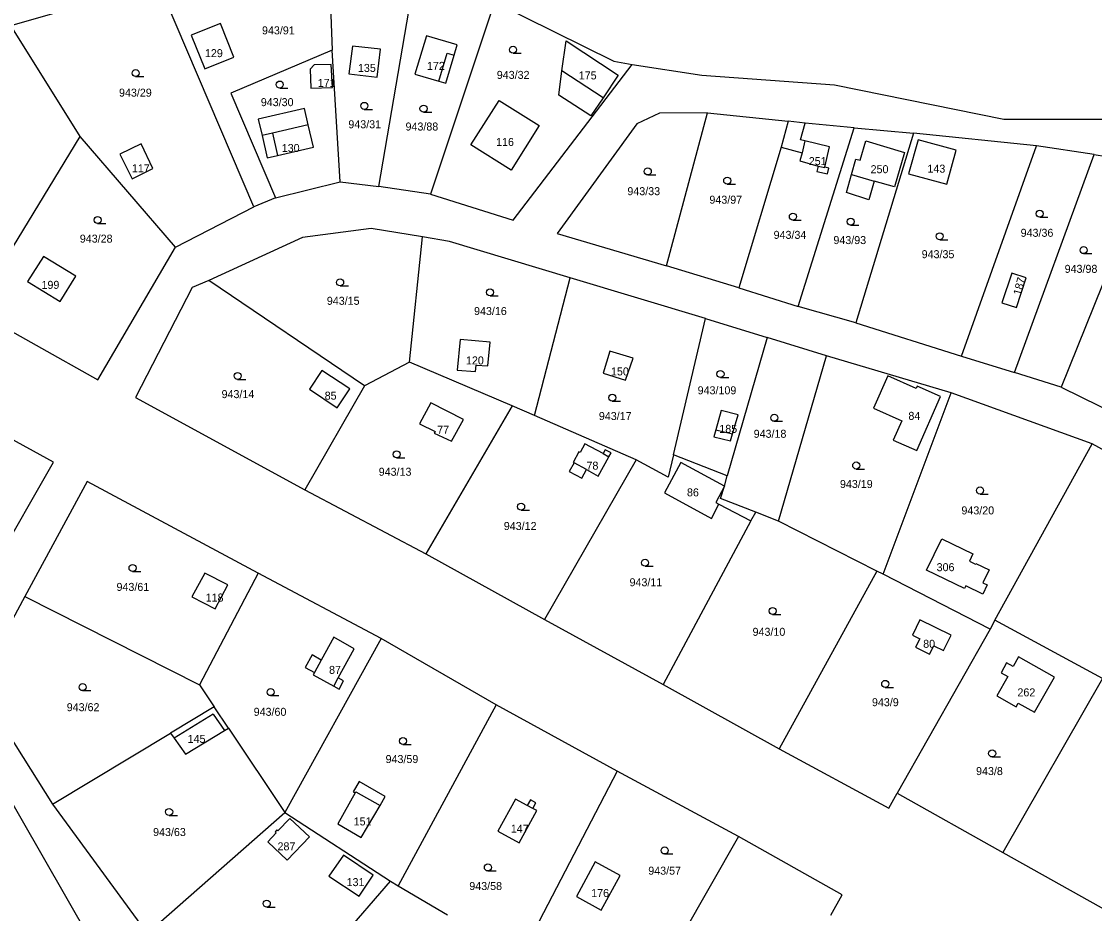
# Model space of a CAD drawing. Extents: x -7476540 to -746055, y -11317203 to -1129777.
# Drawn here: x -751034.6 to -750806.6, y -1131087 to -1130897.4 of the extents above; entities that cross this region are included whole.
import ezdxf

# ---------------------------------------------------------------- set-up
doc = ezdxf.new("R2010")
doc.units = 0
for name, color, linetype in [('Hranice parcel', 7, 'Continuous'), ('Parcelní čísla', 7, 'Continuous'), ('Vnitřní kresba', 7, 'Continuous'), ('Značky kultur', 7, 'Continuous')]:
    doc.layers.add(name, color=color, linetype=linetype)

msp = doc.modelspace()

# ---------------------------------------------------------------- linework, layer by layer
at = {"layer": 'Hranice parcel'}
for p, q in [((-750969.18, -1130887.14), (-750968.63, -1130903.54)), ((-750958.66, -1130932.52), (-750951.18, -1130888.7)), ((-750985.26, -1130936.86), (-751005.24, -1130889.84)), ((-750934.14, -1130893.34), (-750947.69, -1130934.14)), ((-751022.16, -1130921.87), (-751036.87, -1130898.28)), ((-750966.91, -1130931.52), (-750968.63, -1130903.54)), ((-750897.58, -1130949.39), (-750888.87, -1130916.82)), ((-750888.87, -1130916.82), (-750871.74, -1130918.63)), ((-750871.74, -1130918.63), (-750873.22, -1130924.17)), ((-750868.06, -1130919.04), (-750871.74, -1130918.63)), ((-750869.57, -1130958.01), (-750857.66, -1130920.05)), ((-750869.06, -1130922.58), (-750868.06, -1130919.04)), ((-750857.66, -1130920.05), (-750868.06, -1130919.04)), ((-750857.66, -1130920.05), (-750845.08, -1130921.17)), ((-751044.65, -1130958.85), (-751022.16, -1130921.87)), ((-751001.86, -1130945.4), (-751022.16, -1130921.87)), ((-750845.08, -1130921.17), (-750857.31, -1130961.48)), ((-750818.91, -1130923.88), (-750845.08, -1130921.17)), ((-750873.22, -1130924.17), (-750882.2, -1130954.06)), ((-750873.22, -1130924.17), (-750868.74, -1130925.37)), ((-750834.85, -1130968.55), (-750818.91, -1130923.88)), ((-750806.68, -1130925.7), (-750818.91, -1130923.88)), ((-750823.61, -1130972.01), (-750806.68, -1130925.7)), ((-750806.68, -1130925.7), (-750794.6, -1130927.65)), ((-750794.6, -1130927.65), (-750813.68, -1130975.17)), ((-750980.66, -1130934.91), (-750966.91, -1130931.52)), ((-750966.91, -1130931.52), (-750958.66, -1130932.52)), ((-750947.69, -1130934.14), (-750958.66, -1130932.52)), ((-750980.66, -1130934.91), (-750985.26, -1130936.86)), ((-751001.86, -1130945.4), (-750985.26, -1130936.86)), ((-750952.14, -1130969.83), (-750949.38, -1130943.23)), ((-750882.2, -1130954.06), (-750897.58, -1130949.39)), ((-750961.75, -1130974.86), (-750994.79, -1130952.5)), ((-750925.62, -1130981.15), (-750918.05, -1130951.93)), ((-750889.25, -1130960.56), (-750918.05, -1130951.93)), ((-750882.2, -1130954.06), (-750869.57, -1130958.01)), ((-750857.31, -1130961.48), (-750869.57, -1130958.01)), ((-750896.06, -1130989.54), (-750889.25, -1130960.56)), ((-750889.25, -1130960.56), (-750876.18, -1130964.61)), ((-750857.31, -1130961.48), (-750834.85, -1130968.55)), ((-750876.18, -1130964.61), (-750884.66, -1130993.96)), ((-750863.54, -1130968.52), (-750876.18, -1130964.61)), ((-750873.79, -1131003.61), (-750863.54, -1130968.52)), ((-750837.1, -1130976.34), (-750863.54, -1130968.52)), ((-750834.85, -1130968.55), (-750823.61, -1130972.01)), ((-750952.14, -1130969.83), (-750961.75, -1130974.86)), ((-750930.33, -1130979.14), (-750952.14, -1130969.83)), ((-750813.68, -1130975.17), (-750823.61, -1130972.01)), ((-750961.75, -1130974.86), (-750974.42, -1130996.93)), ((-750813.68, -1130975.17), (-750795.61, -1130984.09)), ((-750851.49, -1131014.91), (-750837.1, -1130976.34)), ((-750807.12, -1130987.17), (-750837.1, -1130976.34)), ((-750930.33, -1130979.14), (-750948.69, -1131010.54)), ((-750925.62, -1130981.15), (-750930.33, -1130979.14)), ((-750903.97, -1130990.58), (-750925.62, -1130981.15)), ((-750827.77, -1131024.65), (-750807.12, -1130987.17)), ((-750783.73, -1131000.19), (-750807.12, -1130987.17)), ((-750903.97, -1130990.58), (-750923.45, -1131024.54)), ((-750884.66, -1130993.96), (-750896.06, -1130989.54)), ((-750885.24, -1130996.18), (-750884.66, -1130993.96)), ((-750974.42, -1130996.93), (-750948.69, -1131010.54)), ((-750886.05, -1130998.79), (-750885.24, -1130996.18)), ((-750886.41, -1131000.03), (-750879.66, -1131003.56)), ((-750878.6, -1131001.68), (-750886.05, -1130998.79)), ((-750879.66, -1131003.56), (-750878.6, -1131001.68)), ((-750873.79, -1131003.61), (-750878.6, -1131001.68)), ((-750879.66, -1131003.56), (-750898.3, -1131038.31)), ((-750852.85, -1131014.22), (-750873.79, -1131003.61)), ((-750948.69, -1131010.54), (-750923.45, -1131024.54)), ((-750852.85, -1131014.22), (-750873.59, -1131052.03)), ((-750851.49, -1131014.91), (-750852.85, -1131014.22)), ((-750984.35, -1131014.65), (-750996.76, -1131038.41)), ((-750958.19, -1131028.57), (-750984.35, -1131014.65)), ((-750828.81, -1131026.54), (-750851.49, -1131014.91)), ((-751033.91, -1131019.65), (-750996.76, -1131038.41)), ((-750923.45, -1131024.54), (-750898.3, -1131038.31)), ((-750827.77, -1131024.65), (-750828.81, -1131026.54)), ((-750804.91, -1131037.07), (-750827.77, -1131024.65)), ((-750828.81, -1131026.54), (-750848.52, -1131061.45)), ((-750958.19, -1131028.57), (-750978.69, -1131065.52)), ((-750933.77, -1131042.65), (-750958.19, -1131028.57)), ((-750972.85, -1131032.05), (-750974.36, -1131034.71)), ((-751017.03, -1131097.62), (-751052.97, -1131035.02)), ((-750804.91, -1131037.07), (-750826.11, -1131074)), ((-750996.76, -1131038.41), (-750993.65, -1131043.08)), ((-750967.13, -1131039.32), (-750966.16, -1131037.56)), ((-750898.3, -1131038.31), (-750873.59, -1131052.03)), ((-750993.65, -1131043.08), (-751002.95, -1131048.67)), ((-750990.66, -1131047.57), (-750993.65, -1131043.08)), ((-750933.77, -1131042.65), (-750954.6, -1131081.11)), ((-750908.02, -1131056.72), (-750933.77, -1131042.65)), ((-750990.66, -1131047.57), (-750978.69, -1131065.52)), ((-751028.03, -1131063.75), (-751002.95, -1131048.67)), ((-750908.02, -1131056.72), (-750928.66, -1131096.41)), ((-750882.26, -1131070.62), (-750908.02, -1131056.72)), ((-750848.52, -1131061.45), (-750826.11, -1131074)), ((-751028.03, -1131063.75), (-751007.91, -1131091.26)), ((-751007.91, -1131091.26), (-750978.69, -1131065.52)), ((-750978.69, -1131065.52), (-750956.17, -1131080.13)), ((-750882.26, -1131070.62), (-750894.32, -1131091.73)), ((-750826.11, -1131074), (-750803.42, -1131086.7)), ((-750984.53, -1131112.67), (-750956.17, -1131080.13)), ((-750956.17, -1131080.13), (-750954.6, -1131081.11)), ((-750954.6, -1131081.11), (-750944.07, -1131087.29))]:
    msp.add_line(p, q, dxfattribs=at)
for points in [[(-751036.87, -1130898.28), (-751009.76, -1130890.51), (-751005.24, -1130889.84)], [(-750934.14, -1130893.34), (-750908.78, -1130905.87), (-750904.82, -1130906.58)], [(-750995.69, -1130907.5), (-750989.48, -1130905), (-750992.34, -1130897.88), (-750998.56, -1130900.34), (-750995.69, -1130907.5)], [(-750945.92, -1130910.13), (-750944.45, -1130910.56), (-750942.7, -1130904.58), (-750942.06, -1130902.4), (-750948.54, -1130900.5), (-750951.06, -1130908.63), (-750945.92, -1130910.13)], [(-750911.04, -1130913.69), (-750913.64, -1130917.5), (-750920.43, -1130913.08), (-750919.77, -1130907.92), (-750918.88, -1130901.55), (-750907.81, -1130908.85), (-750911.04, -1130913.69)], [(-750968.63, -1130903.54), (-750990.11, -1130912.67), (-750980.66, -1130934.91)], [(-750958.32, -1130903.33), (-750964.26, -1130902.66), (-750965.03, -1130908.53), (-750959.03, -1130909.3), (-750958.32, -1130903.33)], [(-750973.12, -1130911.62), (-750968.5, -1130911.5), (-750968.79, -1130906.6), (-750972.45, -1130906.68), (-750973.28, -1130907.6), (-750973.12, -1130911.62)], [(-750947.69, -1130934.14), (-750930.15, -1130939.69), (-750904.82, -1130906.58)], [(-750904.82, -1130906.58), (-750890.06, -1130908.85), (-750861.88, -1130910.89), (-750825.89, -1130918.18), (-750800.92, -1130918.19), (-750785.63, -1130919.17), (-750761.64, -1130926.26)], [(-750973.69, -1130919.4), (-750974.49, -1130915.95), (-750984.3, -1130918.23), (-750983.48, -1130921.68)], [(-750939.1, -1130923.63), (-750933.1, -1130914.23), (-750924.58, -1130919.52), (-750930.58, -1130929.06), (-750939.1, -1130923.63)], [(-750888.87, -1130916.82), (-750899.04, -1130916.95), (-750903.89, -1130919.17), (-750920.77, -1130942.5), (-750897.58, -1130949.39)], [(-750983.48, -1130921.68), (-750982.39, -1130926.43), (-750980.22, -1130925.92), (-750972.58, -1130924.14), (-750973.69, -1130919.4)], [(-750868.74, -1130925.37), (-750869.2, -1130927.08), (-750865.31, -1130928.15), (-750865.58, -1130929.3), (-750863.33, -1130929.84), (-750863.03, -1130928.59), (-750863.91, -1130928.38), (-750862.9, -1130924.09), (-750868.13, -1130922.81), (-750869.06, -1130922.58)], [(-750856.4, -1130926.94), (-750855.2, -1130922.78), (-750846.97, -1130925.25), (-750849.09, -1130932.6), (-750853.4, -1130931.35), (-750854.55, -1130935.32), (-750859.34, -1130933.8), (-750858.25, -1130929.94), (-750857.33, -1130926.68), (-750856.4, -1130926.94)], [(-750836.04, -1130924.79), (-750844.11, -1130922.6), (-750846.12, -1130929.84)], [(-751009.17, -1130923.45), (-751013.72, -1130925.66), (-751011.1, -1130930.86), (-751006.69, -1130928.65), (-751009.17, -1130923.45)], [(-750846.12, -1130929.84), (-750838, -1130932.02), (-750836.04, -1130924.79)], [(-750949.38, -1130943.23), (-750960.34, -1130941.46), (-750974.91, -1130943.37), (-750994.79, -1130952.5)], [(-750918.05, -1130951.93), (-750943.66, -1130944.22), (-750949.38, -1130943.23)], [(-751044.65, -1130958.85), (-751018.39, -1130973.56), (-751001.86, -1130945.4)], [(-751026.43, -1130956.96), (-751023.09, -1130951.59), (-751029.93, -1130947.37), (-751033.35, -1130952.7), (-751026.43, -1130956.96)], [(-750994.79, -1130952.5), (-750998.32, -1130953.99), (-751010.42, -1130977.33), (-750974.42, -1130996.93)], [(-750826.29, -1130957.25), (-750823.21, -1130958.25), (-750821.14, -1130951.88), (-750824.19, -1130950.89), (-750826.29, -1130957.25)], [(-750935.51, -1130970.64), (-750935.02, -1130965.55), (-750941.4, -1130965.02), (-750942.04, -1130971.53), (-750938.15, -1130971.85), (-750938, -1130970.48), (-750935.51, -1130970.64)], [(-750911.02, -1130972.18), (-750906.25, -1130973.67), (-750904.61, -1130968.95), (-750909.57, -1130967.48), (-750911.02, -1130972.18)], [(-750964.83, -1130975.53), (-750970.78, -1130971.59), (-750973.43, -1130975.59), (-750967.51, -1130979.57), (-750964.83, -1130975.53)], [(-750853.57, -1130979.6), (-750847.54, -1130982.3), (-750849.38, -1130986.41), (-750844.38, -1130988.59), (-750839.37, -1130977.1), (-750844.3, -1130974.95), (-750844.5, -1130975.41), (-750850.55, -1130972.73), (-750853.57, -1130979.6)], [(-751052.97, -1131035.02), (-751027.78, -1130991.05), (-751058.52, -1130974.24)], [(-750950.02, -1130982.94), (-750946.72, -1130984.59), (-750946.9, -1130984.93), (-750943.27, -1130986.62), (-750940.72, -1130982.05), (-750947.62, -1130978.45), (-750950.02, -1130982.94)], [(-750885.94, -1130980.07), (-750887.07, -1130984.22), (-750887.47, -1130985.68), (-750883.97, -1130986.56), (-750883.52, -1130985.08), (-750882.3, -1130980.99), (-750885.94, -1130980.07)], [(-750912.05, -1130994.03), (-750909.81, -1130989.94), (-750909.35, -1130989.1), (-750910.58, -1130988.43), (-750911.04, -1130989.27), (-750914.89, -1130987.18), (-750915.93, -1130989.02), (-750916.19, -1130988.87), (-750917.37, -1130991.13), (-750917.19, -1130991.23), (-750918.23, -1130993.06), (-750915.56, -1130994.5), (-750914.57, -1130992.65), (-750912.05, -1130994.03)], [(-750896.06, -1130989.54), (-750897.17, -1130994.27), (-750903.97, -1130990.58)], [(-750885.24, -1130996.18), (-750894.5, -1130991.14), (-750897.96, -1130997.59), (-750888.02, -1131003.04), (-750886.41, -1131000.03)], [(-750984.35, -1131014.65), (-751020.67, -1130995.19), (-751033.91, -1131019.65)], [(-750834.21, -1131017.95), (-750842.31, -1131014), (-750839.05, -1131007.34), (-750832.47, -1131010.58), (-750833.2, -1131012.12), (-750831.92, -1131012.74), (-750831.84, -1131012.58), (-750828.99, -1131013.98), (-750830.33, -1131016.72), (-750829.4, -1131017.17), (-750830.36, -1131019.13), (-750833.93, -1131017.38), (-750834.21, -1131017.95)], [(-750990.77, -1131017.18), (-750995.67, -1131014.67), (-750998.41, -1131019.67), (-750993.44, -1131022.26), (-750990.77, -1131017.18)], [(-751033.91, -1131019.65), (-751044.04, -1131038.38), (-751028.03, -1131063.75)], [(-750841.66, -1131031.91), (-750840.75, -1131030.08), (-750838.7, -1131031.1), (-750837.09, -1131027.86), (-750843.7, -1131024.58), (-750845.31, -1131027.82), (-750843.76, -1131028.59), (-750844.66, -1131030.41), (-750841.66, -1131031.91)], [(-750966.16, -1131037.56), (-750967.3, -1131036.93), (-750963.91, -1131030.72), (-750968.24, -1131028.28), (-750970.91, -1131033.12), (-750972.85, -1131032.05)], [(-750823.87, -1131034.49), (-750825.28, -1131033.7), (-750826.47, -1131035.82), (-750825.06, -1131036.61), (-750827.39, -1131040.75), (-750823.24, -1131043.07), (-750822.8, -1131042.28), (-750819.35, -1131044.21), (-750815.13, -1131036.75), (-750822.74, -1131032.47), (-750823.87, -1131034.49)], [(-750974.36, -1131034.71), (-750972.38, -1131035.8), (-750972.66, -1131036.3), (-750968.27, -1131038.7), (-750967.13, -1131039.32)], [(-751002.95, -1131048.67), (-751002.19, -1131049.73), (-750999.74, -1131053.14), (-750991.47, -1131048.07), (-750990.66, -1131047.57)], [(-750873.59, -1131052.03), (-750850.29, -1131064.59), (-750848.52, -1131061.45)], [(-750967.42, -1131067.95), (-750962.44, -1131070.86), (-750958.4, -1131064.01), (-750957.34, -1131062.14), (-750962.87, -1131058.91), (-750964.13, -1131061.13), (-750963.69, -1131061.38), (-750967.42, -1131067.95)], [(-750928.89, -1131071.95), (-750925.13, -1131065.13), (-750925.96, -1131064.67), (-750925.31, -1131063.49), (-750926.49, -1131062.83), (-750927.15, -1131064.02), (-750929.61, -1131062.66), (-750933.37, -1131069.47), (-750928.89, -1131071.95)], [(-750973.44, -1131070.73), (-750977.58, -1131066.83), (-750980.11, -1131069.45), (-750980.33, -1131069.23), (-750980.72, -1131069.63), (-750980.49, -1131069.85), (-750982.3, -1131071.73), (-750978.18, -1131075.63), (-750973.44, -1131070.73)], [(-750862.62, -1131087.31), (-750860.26, -1131083.03), (-750882.26, -1131070.62)], [(-750959.86, -1131078.83), (-750966.18, -1131074.62), (-750969.32, -1131079.06), (-750962.87, -1131083.29), (-750959.86, -1131078.83)], [(-750916.7, -1131083.39), (-750911.43, -1131086.29), (-750907.38, -1131078.93), (-750912.7, -1131075.99), (-750916.7, -1131083.39)]]:
    msp.add_lwpolyline(points, dxfattribs=at)
at = {"layer": 'Vnitřní kresba'}
for p, q in [((-750945.92, -1130910.13), (-750944.17, -1130904.15)), ((-750944.17, -1130904.15), (-750942.7, -1130904.58)), ((-750911.04, -1130913.69), (-750919.77, -1130907.92)), ((-750973.69, -1130919.4), (-750981.31, -1130921.18)), ((-750981.31, -1130921.18), (-750983.48, -1130921.68)), ((-750981.31, -1130921.18), (-750980.22, -1130925.92)), ((-750868.13, -1130922.81), (-750868.74, -1130925.37)), ((-750865.31, -1130928.15), (-750863.93, -1130928.48)), ((-750863.93, -1130928.48), (-750863.91, -1130928.38)), ((-750858.25, -1130929.94), (-750853.4, -1130931.35)), ((-750887.07, -1130984.22), (-750883.52, -1130985.08)), ((-750914.57, -1130992.65), (-750917.19, -1130991.23)), ((-750911.04, -1130989.27), (-750909.81, -1130989.94)), ((-750885.24, -1130996.18), (-750887.11, -1130999.64)), ((-750887.11, -1130999.64), (-750886.41, -1131000.03)), ((-750970.91, -1131033.12), (-750972.38, -1131035.8)), ((-750968.27, -1131038.7), (-750967.3, -1131036.93)), ((-750993.89, -1131044.61), (-751002.19, -1131049.73)), ((-750993.89, -1131044.61), (-750991.47, -1131048.07)), ((-750963.69, -1131061.38), (-750963.54, -1131061.12)), ((-750963.54, -1131061.12), (-750958.4, -1131064.01)), ((-750925.96, -1131064.67), (-750927.15, -1131064.02))]:
    msp.add_line(p, q, dxfattribs=at)
at = {"layer": 'Značky kultur'}
for p, q in [((-750930.17, -1130904.19), (-750928.42, -1130904.19)), ((-751010.36, -1130909.15), (-751008.61, -1130909.15)), ((-750979.74, -1130911.59), (-750977.99, -1130911.59)), ((-750961.77, -1130916.13), (-750960.02, -1130916.13)), ((-750949.19, -1130916.71), (-750947.44, -1130916.71)), ((-750901.54, -1130930.06), (-750899.79, -1130930.06)), ((-750884.65, -1130932.01), (-750882.9, -1130932.01)), ((-751018.44, -1130940.38), (-751016.69, -1130940.38)), ((-750870.7, -1130939.65), (-750868.95, -1130939.65)), ((-750858.43, -1130940.72), (-750856.68, -1130940.72)), ((-750818.26, -1130939.03), (-750816.51, -1130939.03)), ((-750839.5, -1130943.83), (-750837.75, -1130943.83)), ((-750808.93, -1130946.77), (-750807.18, -1130946.77)), ((-750966.91, -1130953.63), (-750965.16, -1130953.63)), ((-750935.06, -1130955.75), (-750933.31, -1130955.75)), ((-750886.09, -1130973.1), (-750884.34, -1130973.1)), ((-750988.69, -1130973.51), (-750986.94, -1130973.51)), ((-750909.07, -1130978.13), (-750907.32, -1130978.13)), ((-750874.66, -1130982.4), (-750872.91, -1130982.4)), ((-750954.91, -1130990.17), (-750953.16, -1130990.17)), ((-750857.24, -1130992.54), (-750855.49, -1130992.54)), ((-750830.94, -1130997.85), (-750829.19, -1130997.85)), ((-750928.45, -1131001.28), (-750926.7, -1131001.28)), ((-750902.11, -1131013.2), (-750900.36, -1131013.2)), ((-751011.01, -1131014.32), (-751009.26, -1131014.32)), ((-750875.01, -1131023.45), (-750873.26, -1131023.45)), ((-750851.08, -1131038.95), (-750849.33, -1131038.95)), ((-751021.63, -1131039.63), (-751019.88, -1131039.63)), ((-750981.68, -1131040.69), (-750979.93, -1131040.69)), ((-750953.55, -1131051.09), (-750951.8, -1131051.09)), ((-750828.36, -1131053.73), (-750826.61, -1131053.73)), ((-751003.24, -1131066.16), (-751001.49, -1131066.16)), ((-750897.95, -1131074.34), (-750896.2, -1131074.34)), ((-750935.51, -1131077.95), (-750933.76, -1131077.95)), ((-750982.49, -1131085.63), (-750980.74, -1131085.63))]:
    msp.add_line(p, q, dxfattribs=at)
for centre in [(-750930.17, -1130903.44), (-751010.36, -1130908.4), (-750979.74, -1130910.84), (-750961.77, -1130915.38), (-750949.19, -1130915.96), (-750901.54, -1130929.31), (-750884.65, -1130931.26), (-751018.44, -1130939.63), (-750870.7, -1130938.9), (-750818.26, -1130938.28), (-750858.43, -1130939.97), (-750839.5, -1130943.08), (-750808.93, -1130946.02), (-750966.91, -1130952.88), (-750935.06, -1130955), (-750988.69, -1130972.76), (-750886.09, -1130972.35), (-750909.07, -1130977.38), (-750874.66, -1130981.65), (-750954.91, -1130989.42), (-750857.24, -1130991.79), (-750830.94, -1130997.1), (-750928.45, -1131000.53), (-750902.11, -1131012.45), (-751011.01, -1131013.57), (-750875.01, -1131022.7), (-751021.63, -1131038.88), (-750981.68, -1131039.94), (-750851.08, -1131038.2), (-750953.55, -1131050.34), (-750828.36, -1131052.98), (-751003.24, -1131065.41), (-750897.95, -1131073.59), (-750935.51, -1131077.2), (-750982.49, -1131084.88)]:
    msp.add_circle(centre, 0.75, dxfattribs=at)

# ---------------------------------------------------------------- texts
at = {"layer": 'Parcelní čísla'}
for s, p in [('943/91', (-750983.51, -1130900.18)), ('129', (-750995.63, -1130905.02)), ('135', (-750963.12, -1130908.16)), ('172', (-750948.46, -1130907.72)), ('943/32', (-750933.62, -1130909.64)), ('175', (-750916.2, -1130909.75)), ('943/29', (-751013.89, -1130913.41)), ('171', (-750971.66, -1130911.33)), ('943/30', (-750983.76, -1130915.43)), ('943/31', (-750965.16, -1130920.13)), ('943/88', (-750953.01, -1130920.61)), ('116', (-750933.77, -1130923.89)), ('130', (-750979.31, -1130925.18)), ('251', (-750867.33, -1130927.96)), ('117', (-751011.16, -1130929.49)), ('250', (-750854.19, -1130929.68)), ('143', (-750842.11, -1130929.56)), ('943/33', (-750905.87, -1130934.35)), ('943/97', (-750888.44, -1130936.16)), ('943/28', (-751022.22, -1130944.43)), ('943/34', (-750874.8, -1130943.63)), ('943/93', (-750862.09, -1130944.74)), ('943/36', (-750822.31, -1130943.19)), ('943/35', (-750843.34, -1130947.74)), ('943/98', (-750812.96, -1130950.85)), ('199', (-751030.36, -1130954.25)), ('943/15', (-750969.73, -1130957.64)), ('943/16', (-750938.45, -1130959.82)), ('120', (-750940.17, -1130970.31)), ('150', (-750909.35, -1130972.65)), ('943/109', (-750890.94, -1130976.66)), ('943/14', (-750992.1, -1130977.47)), ('85', (-750970.19, -1130977.8)), ('943/17', (-750911.93, -1130982.13)), ('84', (-750846.16, -1130982.09)), ('77', (-750946.28, -1130985.04)), ('185', (-750886.33, -1130984.85)), ('943/18', (-750879.04, -1130985.9)), ('78', (-750914.56, -1130992.67)), ('943/13', (-750958.71, -1130993.97)), ('943/19', (-750860.7, -1130996.57)), ('86', (-750893.21, -1130998.35)), ('943/20', (-750834.89, -1131002.18)), ('943/12', (-750932.13, -1131005.5)), ('306', (-750840.16, -1131014.25)), ('943/11', (-750905.41, -1131017.45)), ('943/61', (-751014.42, -1131018.44)), ('118', (-750995.47, -1131020.7)), ('943/10', (-750879.27, -1131027.98)), ('80', (-750843.02, -1131030.53)), ('87', (-750969.26, -1131036.07)), ('262', (-750822.99, -1131040.85)), ('943/9', (-750853.9, -1131042.94)), ('943/62', (-751025, -1131044)), ('943/60', (-750985.28, -1131044.98)), ('145', (-750999.31, -1131050.73)), ('943/59', (-750957.25, -1131055.02)), ('943/8', (-750831.78, -1131057.57)), ('151', (-750964.03, -1131068.27)), ('943/63', (-751006.65, -1131070.53)), ('147', (-750930.64, -1131069.81)), ('287', (-750980.21, -1131073.57)), ('943/57', (-750901.43, -1131078.74)), ('131', (-750965.53, -1131081.17)), ('943/58', (-750939.46, -1131082)), ('176', (-750913.56, -1131083.49))]:
    msp.add_text(s, height=1.7, dxfattribs=at).set_placement(p)
msp.add_text('187', height=1.7, rotation=75, dxfattribs=at).set_placement((-750822.28, -1130955.75))

doc.saveas('drawing.dxf')
